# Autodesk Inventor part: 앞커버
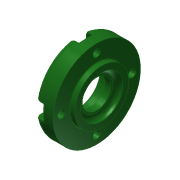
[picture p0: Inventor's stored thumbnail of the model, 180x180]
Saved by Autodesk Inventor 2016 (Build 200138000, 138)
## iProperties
Created: 2015-11
Part Number: 앞커버
Material: 알루미늄 6061
Document SubType Name: Modeling
Designer: mduedu
Density: 1 g/cm^3
Appearance: 매끄러움 - 짙은 산림 녹색
Author: mduedu
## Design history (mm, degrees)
sketch "스케치1"
  geometry: L1 (-7, 0)-(7, 0); L2 (-7, 0)-(-7, 26); L3 (-7, 26)-(4, 26); L4 (4, 26)-(4, 16); L5 (4, 16)-(7, 16); L6 (7, 16)-(7, 0); 2 further points
  constraints: 12 end point, 3 perpendicular, 2 parallel, 1 coincident, 1 horizontal, 1 midpoint
  dimensions: "d0" = 14 distance of L1.start L1.end; "d1" = 52 diameter of L3 L1; "d2" = 3 distance of L4.end L5.end; "d3" = 32 diameter of L5 L1
revolve "회전1" sketch "스케치1" stored, may be unused: angle "d4" = 90 deg
hole "구멍1" diameter "d7" = 25; stored, may be unused: countersink angle "d11" = 90 deg, drill point angle "d13" = 0 deg; dims "d5" = 10, "d6" = 10, "d8" = 6, "d9" = 4, "d10" = 2, "d12" = 3
hole "구멍2" diameter "d16" = 25; stored, may be unused: countersink angle "d20" = 90 deg, drill point angle "d22" = 0 deg; dims "d17" = 6, "d18" = 4, "d19" = 2, "d21" = 7.3, "d62" = 10, "d63" = 10
hole "구멍3" diameter "d25" = 17; stored, may be unused: countersink angle "d29" = 90 deg, drill point angle "d31" = 0 deg; dims "d23" = 10, "d24" = 10, "d26" = 6, "d27" = 4, "d28" = 2, "d30" = 4.2
chamfer "모따기1" distance "d32" = 0.7; stored, may be unused: second distance "d33" = 2, angle "d34" = 30 deg
fillet "모깎기1" dims "d35" = 0.3
fillet "모깎기2" dims "d36" = 3
fillet "모깎기3" dims "d37" = 3
fillet "모깎기4" dims "d38" = 0.3
sketch "스케치3" dims "d61" = 42
  geometry: C1 r 26 at (0, 0) reference; 2 further points
  constraints: 2 vertical alignment, 1 coincident, 2 other
hole "구멍4" sketch "스케치3" at (0, -21) diameter "d44" = 4.5; stored, may be unused: countersink angle "d48" = 90 deg, drill point angle "d50" = 0 deg; dims "d45" = 6, "d46" = 8, "d47" = 4.6, "d49" = 8
sketch "스케치4"
  geometry: L1 (-4, 0)-(-4, -4.69); L2 (4, 0)-(4, -4.69); A1 r 4 centre (0, 0) between (3.614, -1.714) and (-3.614, -1.714) reference; A2 r 26 centre (0, 21) between (-4, -4.69) and (4, -4.69) reference; 1 further point
  constraints: 4 end point, 4 point on circle, 2 tangent, 1 parallel, 1 vertical
extrude "돌출1" cut sketch "스케치4" stored distance "d51" = 0; taper "d52" = 0 deg
fillet "모깎기5" dims "d56" = 0.3
fillet "모깎기6" dims "d57" = 1
node "솔리드1"
pattern_circular "원형 패턴1" dims angle "d54" = 360 deg
